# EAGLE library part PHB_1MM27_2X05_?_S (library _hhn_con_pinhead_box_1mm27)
Pin Header Box-Type, 1.27mm/0.5"/50mil Pitch, 2x05 Circuits, single gates in schematic Note: see library description for an important note about THT-version
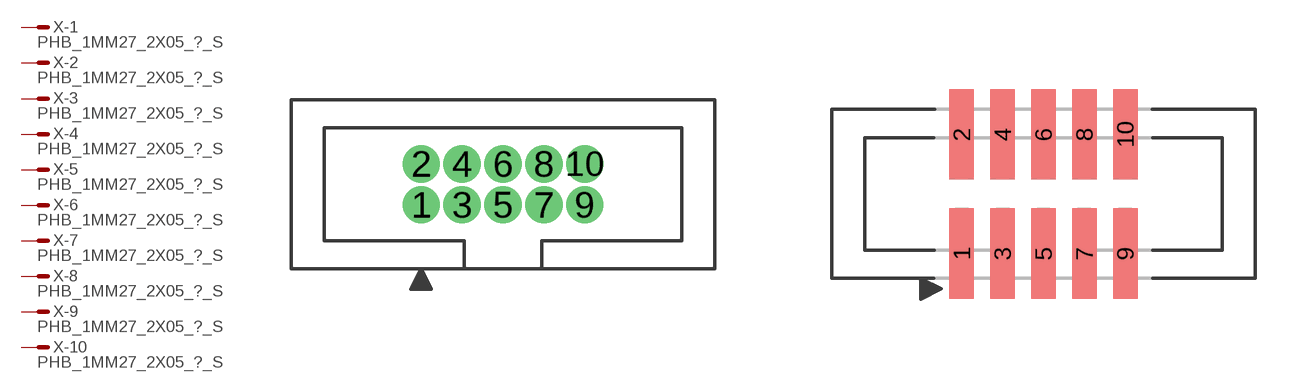
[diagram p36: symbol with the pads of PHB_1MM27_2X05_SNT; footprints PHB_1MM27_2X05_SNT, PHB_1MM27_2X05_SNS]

Designator prefix X; gates -1=M -2=M -3=M -4=M -5=M -6=M -7=M -8=M -9=M -10=M

## PHB_1MM27_2X05_SNT_S  [PHB_1MM27_2X05_SNT]
1  -1:S  pas
2  -2:S  pas
3  -3:S  pas
4  -4:S  pas
5  -5:S  pas
6  -6:S  pas
7  -7:S  pas
8  -8:S  pas
9  -9:S  pas
10  -10:S  pas

## PHB_1MM27_2X05_SNS_S  [PHB_1MM27_2X05_SNS]
Pads as for PHB_1MM27_2X05_SNT

## Footprint PHB_1MM27_2X05_SNT (pad centres in mm)
Pin Header Box-Type, 1.27mm Pitch, 2x05 circuits, Straight, No Locking, THT Important Note: Diameter in this lbr is set to a specific value (NOT 'auto' = 0), this is ignored by actual eagle versions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
drill 0.65 pad 1 round: 1 -2.54,-0.635; 2 -2.54,0.635; 3 -1.27,-0.635; 4 -1.27,0.635; 5 0,-0.635; 6 0,0.635; 7 1.27,-0.635; 8 1.27,0.635; 9 2.54,-0.635; 10 2.54,0.635

## Footprint PHB_1MM27_2X05_SNS (pad centres in mm)
Pin Header Box-Type, 1.27mm Pitch, 2x05 circuits, Straight, No Locking, SMT
smd 0.76 x 2.8: 1 -2.54,-1.85; 2 -2.54,1.85; 3 -1.27,-1.85; 4 -1.27,1.85; 5 0,-1.85; 6 0,1.85; 7 1.27,-1.85; 8 1.27,1.85; 9 2.54,-1.85; 10 2.54,1.85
